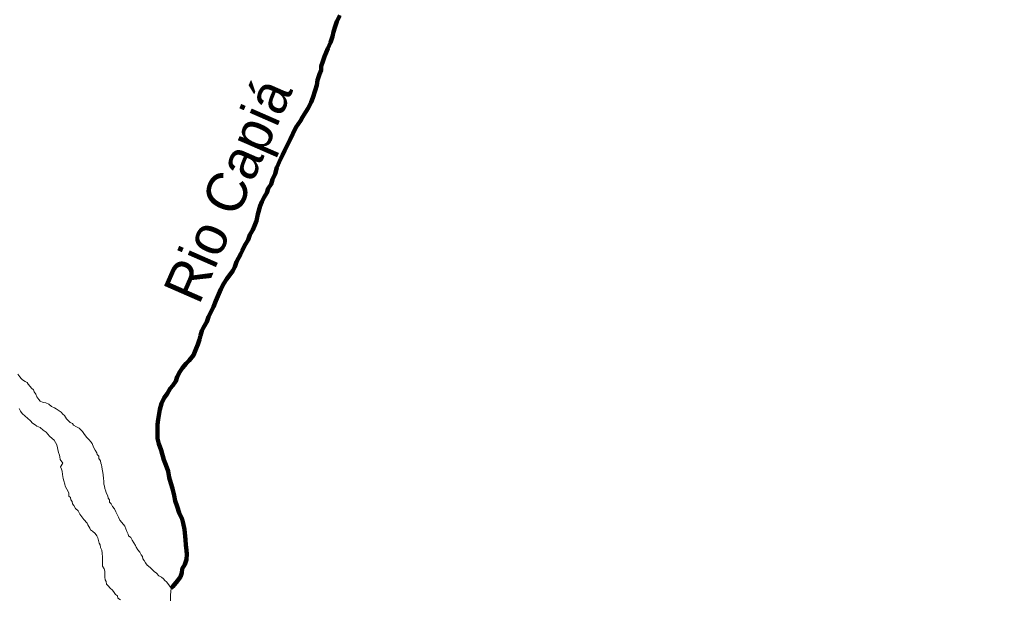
# Model space of a CAD drawing. Extents: x -1643653 to 4543381, y 1624270 to 13878484.
# Drawn here: x 645322 to 657461, y 8930215 to 8937452 of the extents above; entities that cross this region are included whole.
import ezdxf
from ezdxf.enums import TextEntityAlignment as Align

# ---------------------------------------------------------------- set-up
doc = ezdxf.new("R2010")
doc.units = 0
doc.header["$LTSCALE"] = 200
for name, color, linetype, lineweight in [('24', 7, 'Continuous', 25), ('25', 7, 'Continuous', 13), ('57', 7, 'Continuous', 13), ('60', 7, 'Continuous', 13), ('9', 7, 'Continuous', 90)]:
    doc.layers.add(name, color=color, linetype=linetype, lineweight=lineweight)
doc.layers.add('49', color=7, linetype='Continuous')

msp = doc.modelspace()

# ---------------------------------------------------------------- linework, layer by layer
at = {"layer": '24', "lineweight": 53}
for points in [[(649321.9, 8937502.4), (649286.6, 8937427.5), (649266.2, 8937362.5), (649243.4, 8937297.6), (649233.1, 8937237.6), (649207.7, 8937165.2), (649172.4, 8937090.3), (649131.8, 8936990.4), (649111.5, 8936927.9), (649091.2, 8936868), (649088.5, 8936820.5), (649070.7, 8936768), (649042.9, 8936693.1), (649035.1, 8936630.6), (649014.7, 8936565.6), (648986.8, 8936473.2), (648966.5, 8936418.2), (648928.6, 8936343.4), (648898.4, 8936298.5), (648858, 8936233.6), (648830.3, 8936188.7), (648774.8, 8936103.9), (648736.9, 8936024.1), (648704.1, 8935954.2), (648671.2, 8935886.8), (648635.9, 8935819.4), (648605.6, 8935757), (648582.3, 8935707.9)], [(648582.3, 8935707.9), (648534.8, 8935604.7), (648516.9, 8935524.8), (648484, 8935454.9), (648466.2, 8935397.4), (648428.4, 8935342.6), (648410.7, 8935290.1), (648377.9, 8935235.2), (648347.6, 8935175.3), (648327.3, 8935125.4), (648299.3, 8935022.9), (648281.4, 8934937.9), (648258.6, 8934878), (648238.3, 8934825.6), (648200.5, 8934765.7), (648180.2, 8934700.8), (648132.3, 8934628.4), (648104.5, 8934563.5), (648085.8, 8934528.5)], [(648085.8, 8934528.5), (648033.8, 8934426.2), (648013.5, 8934366.3), (647988.2, 8934313.9), (647947.9, 8934264), (647910.1, 8934214.2), (647874.8, 8934156.8), (647837, 8934086.9), (647811.7, 8934027), (647776.2, 8933942.1), (647745.8, 8933864.7), (647682.7, 8933739.9), (647662.4, 8933680), (647619.5, 8933610.1), (647601.8, 8933565.2), (647584, 8933507.7), (647568.8, 8933460.2), (647550.9, 8933395.3), (647530.7, 8933347.8), (647495.3, 8933265.4), (647439.9, 8933195.7), (647404.7, 8933158.3), (647359.4, 8933106), (647324.1, 8933053.6), (647291.3, 8932993.8), (647273.5, 8932938.8), (647235.8, 8932886.4), (647205.5, 8932846.6), (647167.7, 8932781.7), (647129.9, 8932729.3), (647097.1, 8932659.4), (647076.7, 8932584.5), (647056.1, 8932459.4), (647048.3, 8932399.4), (647045.5, 8932349.4), (647045.2, 8932271.8), (647047.4, 8932221.8), (647064.6, 8932156.6), (647091.8, 8932078.9), (647126.2, 8931956.1), (647148.4, 8931893.4), (647180.6, 8931815.7), (647192.7, 8931735.5), (647212.4, 8931665.4), (647232.1, 8931600.2), (647254.2, 8931512.5), (647268.9, 8931444.8), (647291.1, 8931374.7), (647315.7, 8931294.4), (647352.9, 8931216.7), (647365.1, 8931166.6), (647382.3, 8931086.4), (647391.9, 8931006.3), (647396.7, 8930958.7), (647401.4, 8930898.6), (647408.5, 8930828.5), (647413.3, 8930780.9), (647410.5, 8930713.4), (647387.7, 8930650.9), (647354.9, 8930598.5), (647349.7, 8930548.5), (647331.9, 8930496.1), (647296.6, 8930446.2), (647238.7, 8930376.4), (647217.5, 8930357.5)]]:
    msp.add_lwpolyline(points, dxfattribs=at)
at = {"layer": '25'}
for points in [[(645303.2, 8933024.8), (645325.5, 8932994.6), (645342.8, 8932974.4), (645360.2, 8932954.3), (645395.1, 8932936.6), (645420, 8932921.4), (645432.3, 8932901.3), (645454.6, 8932873.6), (645474.5, 8932853.4), (645496.8, 8932830.7), (645506.6, 8932808.1), (645526.4, 8932775.5), (645541.2, 8932742.8), (645563.4, 8932710.1), (645583.3, 8932690), (645618.1, 8932672.2), (645653.1, 8932669.5), (645690.5, 8932651.7), (645722.8, 8932621.4), (645760.2, 8932606.2), (645782.6, 8932593.5), (645820, 8932570.7), (645842.3, 8932550.6), (645864.7, 8932527.9), (645887.1, 8932512.7), (645899.4, 8932490.1), (645909.2, 8932470), (645929.1, 8932449.8), (645953.9, 8932424.6), (645983.8, 8932409.4), (645998.7, 8932389.3), (646033.5, 8932369), (646068.4, 8932353.8), (646090.8, 8932331.1), (646108.1, 8932311), (646128, 8932288.3), (646147.7, 8932258.1), (646162.6, 8932235.5), (646192.3, 8932205.2), (646214.7, 8932182.6), (646232, 8932162.4), (646249.2, 8932117.2), (646266.4, 8932077.1), (646288.7, 8932044.4), (646293.5, 8932024.3), (646313.4, 8932004.2), (646313.1, 8931974.1), (646332.9, 8931946.5), (646340.2, 8931916.4), (646345.1, 8931896.3), (646349.9, 8931868.7), (646357.2, 8931841.2), (646361.8, 8931801.1), (646366.6, 8931771), (646371.3, 8931725.9), (646376, 8931690.8), (646378.2, 8931653.2), (646383.1, 8931630.7), (646387.8, 8931600.6), (646400.1, 8931568), (646407.4, 8931545.4), (646424.7, 8931510.2), (646429.4, 8931477.7), (646446.8, 8931457.5), (646449, 8931427.5), (646468.9, 8931407.3), (646486.2, 8931374.6), (646508.4, 8931344.4), (646525.7, 8931306.8), (646542.9, 8931276.6), (646557.7, 8931241.5)], [(645677.7, 8932278.8), (645655.3, 8932301.4), (645620.5, 8932329.2), (645580.8, 8932359.5), (645540.9, 8932377.3), (645518.5, 8932395), (645483.6, 8932415.2), (645461.3, 8932445.4), (645424.1, 8932475.7), (645394.3, 8932503.4), (645354.5, 8932536.3), (645334.7, 8932566.4), (645317.4, 8932596.6)], [(646584.9, 8930212.3), (646552.5, 8930232.6), (646547.7, 8930260.2), (646522.8, 8930277.8), (646505.5, 8930300.5), (646485.7, 8930330.7), (646453.4, 8930358.4), (646431.1, 8930386.1), (646411.3, 8930406.3), (646404, 8930438.9), (646394.2, 8930461.5), (646386.9, 8930494.1), (646387.2, 8930524.1), (646387.3, 8930544.1), (646387.5, 8930569.2), (646380.2, 8930599.2), (646360.5, 8930631.9), (646360.6, 8930651.9), (646360.8, 8930672), (646361.3, 8930742.1), (646356.7, 8930792.2), (646349.5, 8930829.8), (646334.7, 8930862.4), (646330, 8930897.5), (646317.6, 8930917.6), (646307.9, 8930952.7), (646300.6, 8930985.3), (646288.3, 8931007.9), (646266, 8931038.1), (646236.2, 8931068.4), (646208.8, 8931083.6), (646201.5, 8931103.6), (646189.1, 8931126.2), (646176.8, 8931146.4), (646169.4, 8931166.4), (646124.8, 8931211.8), (646077.8, 8931279.7), (646055.6, 8931322.4), (646020.8, 8931350.2), (646001, 8931387.9), (645983.7, 8931410.5), (645981.4, 8931438.1), (645964.1, 8931458.2), (645959.3, 8931485.8), (645939.4, 8931505.9), (645937.2, 8931541), (645929.8, 8931561.1), (645912.6, 8931593.7), (645895.3, 8931628.9), (645890.5, 8931654), (645875.8, 8931696.6), (645868.5, 8931724.2), (645861.4, 8931774.3), (645854.2, 8931814.4), (645846.9, 8931839.5), (645834.6, 8931869.6), (645865, 8931914.5), (645832.8, 8931959.8), (645828.1, 8931994.9), (645823.2, 8932014.9), (645811, 8932050.1), (645803.8, 8932085.2), (645796.4, 8932107.7), (645789.2, 8932142.8), (645774.4, 8932173), (645754.6, 8932203.1), (645732.3, 8932223.3), (645697.5, 8932253.6), (645677.7, 8932278.8)], [(646557.7, 8931241.5), (646577.4, 8931206.3), (646599.7, 8931176.1), (646636.8, 8931128.3), (646661.4, 8931063.1), (646681.1, 8931030.4), (646683.5, 8931010.3), (646713.3, 8930987.6), (646730.6, 8930957.4), (646750.3, 8930922.3), (646772.6, 8930889.6), (646779.9, 8930867), (646802.2, 8930836.8), (646824.5, 8930804.1), (646841.8, 8930773.9), (646859.1, 8930751.3), (646861.3, 8930721.2), (646878.7, 8930701.1), (646898.5, 8930673.4), (646918.3, 8930643.3), (646953.1, 8930613), (646975.5, 8930595.3), (647005.2, 8930562.6), (647035.1, 8930542.3), (647064.9, 8930512.1), (647097.2, 8930494.4), (647119.6, 8930474.2), (647137, 8930454.1), (647156.8, 8930433.9), (647174.2, 8930413.7), (647218.7, 8930355.9), (647208.1, 8930270.8), (647207.9, 8930250.8), (647207.7, 8930218.2), (647210, 8930198.2)]]:
    msp.add_lwpolyline(points, dxfattribs=at)
at = {"layer": '57'}
for points in [[(646557.7, 8931241.5), (646542.9, 8931276.6), (646525.7, 8931306.8), (646508.4, 8931344.4), (646486.2, 8931374.6), (646468.9, 8931407.3), (646449, 8931427.5), (646446.8, 8931457.5), (646429.4, 8931477.7), (646424.7, 8931510.2), (646407.4, 8931545.4), (646400.1, 8931568), (646387.8, 8931600.6), (646383.1, 8931630.7), (646378.2, 8931653.2), (646376, 8931690.8), (646371.3, 8931725.9), (646366.6, 8931771), (646361.8, 8931801.1), (646357.2, 8931841.2), (646349.9, 8931868.7), (646345.1, 8931896.3), (646340.2, 8931916.4), (646332.9, 8931946.5), (646313.1, 8931974.1), (646313.4, 8932004.2), (646293.5, 8932024.3), (646288.7, 8932044.4), (646266.4, 8932077.1), (646249.2, 8932117.2), (646232, 8932162.4), (646214.7, 8932182.6), (646192.3, 8932205.2), (646162.6, 8932235.5), (646147.7, 8932258.1), (646128, 8932288.3), (646108.1, 8932311), (646090.8, 8932331.1), (646068.4, 8932353.8), (646033.5, 8932369), (645998.7, 8932389.3), (645983.8, 8932409.4), (645953.9, 8932424.6), (645929.1, 8932449.8), (645909.2, 8932470), (645899.4, 8932490.1), (645887.1, 8932512.7), (645864.7, 8932527.9), (645842.3, 8932550.6), (645820, 8932570.7), (645782.6, 8932593.5), (645760.2, 8932606.2), (645722.8, 8932621.4), (645690.5, 8932651.7), (645653.1, 8932669.5), (645618.1, 8932672.2), (645583.3, 8932690), (645563.4, 8932710.1), (645541.2, 8932742.8), (645526.4, 8932775.5), (645506.6, 8932808.1), (645496.8, 8932830.7), (645474.5, 8932853.4), (645454.6, 8932873.6), (645432.3, 8932901.3), (645420, 8932921.4), (645395.1, 8932936.6), (645360.2, 8932954.3), (645342.8, 8932974.4), (645325.5, 8932994.6), (645303.2, 8933024.8)], [(645303.2, 8933024.8), (645325.5, 8932994.6), (645342.8, 8932974.4), (645360.2, 8932954.3), (645395.1, 8932936.6), (645420, 8932921.4), (645432.3, 8932901.3), (645454.6, 8932873.6), (645474.5, 8932853.4), (645496.8, 8932830.7), (645506.6, 8932808.1), (645526.4, 8932775.5), (645541.2, 8932742.8), (645563.4, 8932710.1), (645583.3, 8932690), (645618.1, 8932672.2), (645653.1, 8932669.5), (645690.5, 8932651.7), (645722.8, 8932621.4), (645760.2, 8932606.2), (645782.6, 8932593.5), (645820, 8932570.7), (645842.3, 8932550.6), (645864.7, 8932527.9), (645887.1, 8932512.7), (645899.4, 8932490.1), (645909.2, 8932470), (645929.1, 8932449.8), (645953.9, 8932424.6), (645983.8, 8932409.4), (645998.7, 8932389.3), (646033.5, 8932369), (646068.4, 8932353.8), (646090.8, 8932331.1), (646108.1, 8932311), (646128, 8932288.3), (646147.7, 8932258.1), (646162.6, 8932235.5), (646192.3, 8932205.2), (646214.7, 8932182.6), (646232, 8932162.4), (646249.2, 8932117.2), (646266.4, 8932077.1), (646288.7, 8932044.4), (646293.5, 8932024.3), (646313.4, 8932004.2), (646313.1, 8931974.1), (646332.9, 8931946.5), (646340.2, 8931916.4), (646345.1, 8931896.3), (646349.9, 8931868.7), (646357.2, 8931841.2), (646361.8, 8931801.1), (646366.6, 8931771), (646371.3, 8931725.9), (646376, 8931690.8), (646378.2, 8931653.2), (646383.1, 8931630.7), (646387.8, 8931600.6), (646400.1, 8931568), (646407.4, 8931545.4), (646424.7, 8931510.2), (646429.4, 8931477.7), (646446.8, 8931457.5), (646449, 8931427.5), (646468.9, 8931407.3), (646486.2, 8931374.6), (646508.4, 8931344.4), (646525.7, 8931306.8), (646542.9, 8931276.6), (646557.7, 8931241.5)], [(647210, 8930198.2), (647207.7, 8930218.2), (647207.9, 8930250.8), (647208.1, 8930270.8), (647218.7, 8930355.9), (647174.2, 8930413.7), (647156.8, 8930433.9), (647137, 8930454.1), (647119.6, 8930474.2), (647097.2, 8930494.4), (647064.9, 8930512.1), (647035.1, 8930542.3), (647005.2, 8930562.6), (646975.5, 8930595.3), (646953.1, 8930613), (646918.3, 8930643.3), (646898.5, 8930673.4), (646878.7, 8930701.1), (646861.3, 8930721.2), (646859.1, 8930751.3), (646841.8, 8930773.9), (646824.5, 8930804.1), (646802.2, 8930836.8), (646779.9, 8930867), (646772.6, 8930889.6), (646750.3, 8930922.3), (646730.6, 8930957.4), (646713.3, 8930987.6), (646683.5, 8931010.3), (646681.1, 8931030.4), (646661.4, 8931063.1), (646636.8, 8931128.3), (646599.7, 8931176.1), (646577.4, 8931206.3), (646557.7, 8931241.5)], [(646557.7, 8931241.5), (646577.4, 8931206.3), (646599.7, 8931176.1), (646636.8, 8931128.3), (646661.4, 8931063.1), (646681.1, 8931030.4), (646683.5, 8931010.3), (646713.3, 8930987.6), (646730.6, 8930957.4), (646750.3, 8930922.3), (646772.6, 8930889.6), (646779.9, 8930867), (646802.2, 8930836.8), (646824.5, 8930804.1), (646841.8, 8930773.9), (646859.1, 8930751.3), (646861.3, 8930721.2), (646878.7, 8930701.1), (646898.5, 8930673.4), (646918.3, 8930643.3), (646953.1, 8930613), (646975.5, 8930595.3), (647005.2, 8930562.6), (647035.1, 8930542.3), (647064.9, 8930512.1), (647097.2, 8930494.4), (647119.6, 8930474.2), (647137, 8930454.1), (647156.8, 8930433.9), (647174.2, 8930413.7), (647218.7, 8930355.9), (647208.1, 8930270.8), (647207.9, 8930250.8), (647207.7, 8930218.2), (647210, 8930198.2)]]:
    msp.add_lwpolyline(points, dxfattribs=at)
at = {"layer": '60', "lineweight": 25}
msp.add_spline([(814781, 9009175.5), (814787.2, 9009173.4), (814796.9, 9009173.4), (814799.4, 9009172.4), (814805.1, 9009174.5), (814805.6, 9009176.5), (814811.7, 9009179.5), (814811.7, 9009179.5), (814801.5, 9009181), (814790.7, 9009181.5), (814784.1, 9009183.1), (814777.4, 9009185.1), (814778.4, 9009175.5)], degree=3, dxfattribs=at)
at = {"layer": '9'}
for points in [[(649321.9, 8937502.4), (649286.6, 8937427.5), (649266.2, 8937362.5), (649243.4, 8937297.6), (649233.1, 8937237.6), (649207.7, 8937165.2), (649172.4, 8937090.3), (649131.8, 8936990.4), (649111.5, 8936927.9), (649091.2, 8936868), (649088.5, 8936820.5), (649070.7, 8936768), (649042.9, 8936693.1), (649035.1, 8936630.6), (649014.7, 8936565.6), (648986.8, 8936473.2), (648966.5, 8936418.2), (648928.6, 8936343.4), (648898.4, 8936298.5), (648858, 8936233.6), (648830.3, 8936188.7), (648774.8, 8936103.9), (648736.9, 8936024.1), (648704.1, 8935954.2), (648671.2, 8935886.8), (648635.9, 8935819.4), (648605.6, 8935757), (648582.3, 8935707.9)], [(648582.3, 8935707.9), (648534.8, 8935604.7), (648516.9, 8935524.8), (648484, 8935454.9), (648466.2, 8935397.4), (648428.4, 8935342.6), (648410.7, 8935290.1), (648377.9, 8935235.2), (648347.6, 8935175.3), (648327.3, 8935125.4), (648299.3, 8935022.9), (648281.4, 8934937.9), (648258.6, 8934878), (648238.3, 8934825.6), (648200.5, 8934765.7), (648180.2, 8934700.8), (648132.3, 8934628.4), (648104.5, 8934563.5), (648085.8, 8934528.5)], [(648085.8, 8934528.5), (648033.8, 8934426.2), (648013.5, 8934366.3), (647988.2, 8934313.9), (647947.9, 8934264), (647910.1, 8934214.2), (647874.8, 8934156.8), (647837, 8934086.9), (647811.7, 8934027), (647776.2, 8933942.1), (647745.8, 8933864.7), (647682.7, 8933739.9), (647662.4, 8933680), (647619.5, 8933610.1), (647601.8, 8933565.2), (647584, 8933507.7), (647568.8, 8933460.2), (647550.9, 8933395.3), (647530.7, 8933347.8), (647495.3, 8933265.4), (647439.9, 8933195.7), (647404.7, 8933158.3), (647359.4, 8933106), (647324.1, 8933053.6), (647291.3, 8932993.8), (647273.5, 8932938.8), (647235.8, 8932886.4), (647205.5, 8932846.6), (647167.7, 8932781.7), (647129.9, 8932729.3), (647097.1, 8932659.4), (647076.7, 8932584.5), (647056.1, 8932459.4), (647048.3, 8932399.4), (647045.5, 8932349.4), (647045.2, 8932271.8), (647047.4, 8932221.8), (647064.6, 8932156.6), (647091.8, 8932078.9), (647126.2, 8931956.1), (647148.4, 8931893.4), (647180.6, 8931815.7), (647192.7, 8931735.5), (647212.4, 8931665.4), (647232.1, 8931600.2), (647254.2, 8931512.5), (647268.9, 8931444.8), (647291.1, 8931374.7), (647315.7, 8931294.4), (647352.9, 8931216.7), (647365.1, 8931166.6), (647382.3, 8931086.4), (647391.9, 8931006.3), (647396.7, 8930958.7), (647401.4, 8930898.6), (647408.5, 8930828.5), (647413.3, 8930780.9), (647410.5, 8930713.4), (647387.7, 8930650.9), (647354.9, 8930598.5), (647349.7, 8930548.5), (647331.9, 8930496.1), (647296.6, 8930446.2), (647238.7, 8930376.4), (647217.5, 8930357.5)]]:
    msp.add_lwpolyline(points, dxfattribs=at)

# ---------------------------------------------------------------- texts
at = {"layer": '49'}
msp.add_text('Rio Capiá', height=500, rotation=66.381, dxfattribs=at).set_placement((648152.9, 8935223.9), align=Align.CENTER)

doc.saveas('drawing.dxf')
